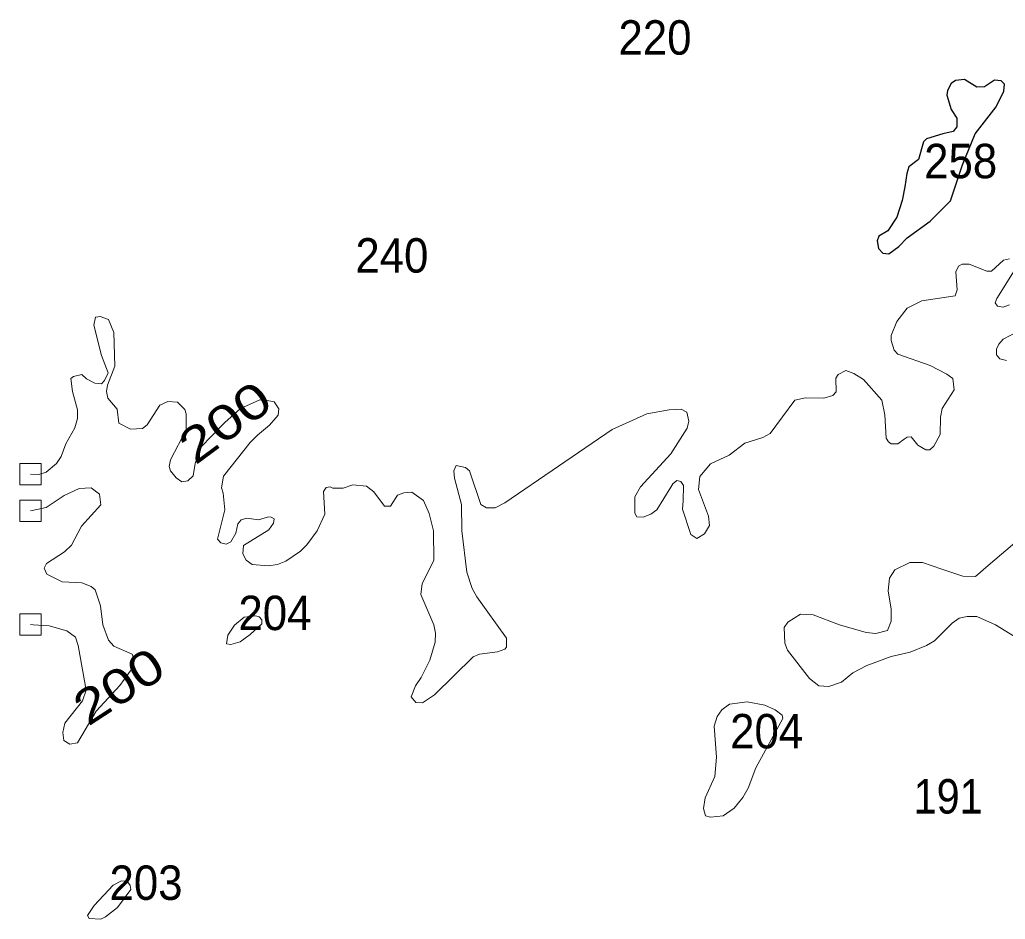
# Model space of a CAD drawing. Extents: x 499.9 to 555.3, y 9281.5 to 9336.8.
# Drawn here: x 499.95 to 504.528, y 9297.621 to 9301.799 of the extents above; entities that cross this region are included whole.
import ezdxf
from ezdxf.enums import TextEntityAlignment as Align

# ---------------------------------------------------------------- set-up
doc = ezdxf.new("R2010")
doc.units = 0
doc.header["$LTSCALE"] = 0.064
for name, color, linetype, lineweight in [('1', 7, 'Continuous', 25), ('2', 7, 'Continuous', 13), ('62', 7, 'Continuous', 13)]:
    doc.layers.add(name, color=color, linetype=linetype, lineweight=lineweight)
doc.layers.add('21', color=7, linetype='Continuous')
doc.layers.add('61', color=7, linetype='Continuous')

msp = doc.modelspace()

# ---------------------------------------------------------------- linework, layer by layer
at = {"layer": '1'}
msp.add_lwpolyline([(504.1796, 9300.8642), (504.2734, 9300.9584), (504.329, 9301.1256), (504.3885, 9301.2695), (504.4858, 9301.3947), (504.5208, 9301.4678), (504.5246, 9301.4992), (504.509, 9301.515), (504.4779, 9301.5182), (504.4309, 9301.4874), (504.396, 9301.4855), (504.3393, 9301.5216), (504.2966, 9301.5169), (504.2759, 9301.5031), (504.2588, 9301.47), (504.2569, 9301.4494), (504.276, 9301.3819), (504.3026, 9301.342), (504.3024, 9301.3009), (504.2863, 9301.2798), (504.2384, 9301.2693), (504.1626, 9301.2456), (504.1474, 9301.2317), (504.1248, 9301.1502), (504.0797, 9301.1159), (504.0707, 9301.0856), (504.0618, 9301.0233), (504.0494, 9300.9591), (504.0241, 9300.8822), (503.9817, 9300.8184), (503.9407, 9300.7934), (503.9328, 9300.7716), (503.9389, 9300.7364), (503.9585, 9300.715), (503.9867, 9300.7111), (504.0329, 9300.7458), (504.0722, 9300.7865)], close=True, dxfattribs=at)
at = {"layer": '2'}
for points in [[(504.2841, 9300.1327), (504.2567, 9300.1531), (504.1788, 9300.1931), (504.0292, 9300.2456), (504.0111, 9300.2648), (503.9975, 9300.3091), (503.9977, 9300.332), (504.0249, 9300.3981), (504.0717, 9300.4597), (504.1398, 9300.4934), (504.2946, 9300.5164), (504.3043, 9300.5449), (504.2984, 9300.628), (504.3111, 9300.6543), (504.3271, 9300.6634), (504.3602, 9300.6638), (504.4428, 9300.6318), (504.4638, 9300.6307), (504.5191, 9300.6825), (504.548, 9300.6884)], [(504.5696, 9300.6332), (504.4893, 9300.5049), (504.4816, 9300.4837), (504.4919, 9300.4689), (504.5181, 9300.4642), (504.5475, 9300.4749)], [(500, 9299.6881), (500.0388, 9299.6869), (500.0733, 9299.6981), (500.1216, 9299.7377), (500.1424, 9299.7701), (500.1644, 9299.829), (500.2058, 9299.9043), (500.2188, 9299.9463), (500.2189, 9299.9869), (500.1947, 9300.0722), (500.1878, 9300.1327), (500.1997, 9300.1425), (500.2379, 9300.1511), (500.2604, 9300.131), (500.2986, 9300.1118), (500.3294, 9300.1074), (500.3441, 9300.123), (500.361, 9300.1597), (500.33, 9300.2403), (500.2936, 9300.3797), (500.3026, 9300.4173), (500.3235, 9300.4209), (500.363, 9300.406), (500.3874, 9300.3468), (500.3917, 9300.1899), (500.3577, 9300.1018), (500.353, 9300.0726), (500.3598, 9300.0413), (500.4032, 9299.9906), (500.4108, 9299.9254), (500.4641, 9299.8972), (500.5197, 9299.9004), (500.5419, 9299.9178), (500.6012, 9300.0082), (500.6384, 9300.0254), (500.6836, 9300.0222), (500.7168, 9299.9892), (500.7234, 9299.9692), (500.723, 9299.8942), (500.6503, 9299.7544), (500.644, 9299.7244), (500.6504, 9299.7036), (500.6762, 9299.6707), (500.7026, 9299.6525), (500.7309, 9299.6578), (500.7562, 9299.6803), (500.7644, 9299.738), (500.7879, 9299.81), (500.9028, 9299.929), (500.9755, 9299.993), (501.065, 9300.0342), (501.0917, 9300.0326), (501.1317, 9300.0243), (501.1532, 9299.9912), (501.1498, 9299.9621), (501.1098, 9299.9162), (501.0546, 9299.87), (501.0207, 9299.8361), (500.8971, 9299.6789), (500.8875, 9299.6254), (500.8955, 9299.6008), (500.9032, 9299.523), (500.8687, 9299.3861), (500.8844, 9299.3688), (500.909, 9299.3635), (500.9308, 9299.3739), (500.9541, 9299.4147), (500.9629, 9299.4583), (500.9782, 9299.477), (501.0053, 9299.4845), (501.0595, 9299.4768), (501.1062, 9299.4908), (501.1187, 9299.4893), (501.1315, 9299.4811), (501.1292, 9299.4607), (501.1078, 9299.4302), (500.9901, 9299.3577), (500.9862, 9299.3178), (501.0021, 9299.2891), (501.0298, 9299.2683), (501.1052, 9299.2619), (501.1476, 9299.2682), (501.1866, 9299.2842), (501.254, 9299.3309), (501.284, 9299.3596), (501.331, 9299.4245), (501.3677, 9299.5031), (501.3618, 9299.608), (501.3738, 9299.626), (501.3922, 9299.6302), (501.404, 9299.6233), (501.4521, 9299.6232), (501.4977, 9299.6391), (501.5614, 9299.6327), (501.595, 9299.6061)], [(504.5895, 9300.352), (504.5177, 9300.3149), (504.4975, 9300.2928), (504.4877, 9300.2689), (504.4869, 9300.2428), (504.5024, 9300.2242), (504.5329, 9300.2166)], [(501.7342, 9299.6023), (501.7715, 9299.6054), (501.8251, 9299.5656), (501.8524, 9299.5053), (501.8723, 9299.425), (501.8741, 9299.288), (501.8192, 9299.1808), (501.8137, 9299.1294), (501.8739, 9298.9889), (501.882, 9298.9499), (501.8803, 9298.9078), (501.8547, 9298.8251), (501.8155, 9298.7437), (501.7883, 9298.7048), (501.768, 9298.654), (501.7893, 9298.6275), (501.8215, 9298.6269), (501.8769, 9298.6631), (502.0556, 9298.84), (502.085, 9298.8529), (502.1687, 9298.863), (502.2034, 9298.8753), (502.2114, 9298.8855), (502.2106, 9298.9259), (502.0728, 9299.1193), (502.0522, 9299.1576), (502.027, 9299.2332), (502.003, 9299.425), (502.0014, 9299.5476), (501.9693, 9299.6693), (501.9667, 9299.7042), (501.9769, 9299.7292), (502.0204, 9299.72), (502.0398, 9299.7035), (502.0914, 9299.548), (502.1176, 9299.5323), (502.1592, 9299.5322), (502.203, 9299.5549), (502.7025, 9299.8957), (502.8635, 9299.9689), (502.966, 9299.9876), (503.023, 9299.9906), (503.0491, 9299.9762), (503.0583, 9299.9348), (503.0506, 9299.9023), (502.975, 9299.7832), (502.8328, 9299.6301), (502.8068, 9299.5827), (502.807, 9299.5071), (502.8172, 9299.4896), (502.8457, 9299.4883), (502.8809, 9299.502), (502.9095, 9299.5225), (502.9746, 9299.628), (502.9838, 9299.643), (503.0019, 9299.6583), (503.021, 9299.6537), (503.0329, 9299.6357), (503.0316, 9299.5651), (503.0283, 9299.5261), (503.0678, 9299.4089), (503.0956, 9299.3897), (503.1305, 9299.4106), (503.1535, 9299.4505), (503.1499, 9299.4928), (503.103, 9299.6178), (503.1089, 9299.6773), (503.1587, 9299.736), (503.2454, 9299.7773), (503.3178, 9299.8322), (503.4021, 9299.8589), (503.4363, 9299.8775), (503.5503, 9300.0318), (503.5996, 9300.0436), (503.6853, 9300.0419), (503.7266, 9300.0532), (503.7427, 9300.0703), (503.7411, 9300.134), (503.752, 9300.1506), (503.788, 9300.1692), (503.8248, 9300.1566), (503.8693, 9300.1281), (503.9552, 9300.0314), (503.9683, 9299.964), (503.9749, 9299.8555), (503.9854, 9299.8388), (503.9978, 9299.8289), (504.0285, 9299.83), (504.0577, 9299.8514), (504.0717, 9299.8606), (504.0902, 9299.8625), (504.121, 9299.8225), (504.1596, 9299.8017), (504.177, 9299.8018), (504.1956, 9299.8189)], [(504.1956, 9299.8189), (504.2262, 9299.8733), (504.2266, 9299.9534), (504.2344, 9299.9932), (504.2913, 9300.0793), (504.2841, 9300.1327)], [(500, 9298.99), (500.0126, 9298.9892), (500.0862, 9298.9845), (500.1695, 9298.9607), (500.2092, 9298.9318), (500.2221, 9298.8931), (500.2588, 9298.6855), (500.241, 9298.6359), (500.1596, 9298.5318), (500.1497, 9298.4878), (500.1555, 9298.4519), (500.1833, 9298.4336), (500.2189, 9298.4399), (500.3044, 9298.5876), (500.4155, 9298.7066), (500.475, 9298.7899), (500.4828, 9298.8267), (500.4723, 9298.8519), (500.3868, 9298.8897), (500.3619, 9298.9172), (500.3368, 9298.9881), (500.3254, 9299.0772), (500.3011, 9299.1509), (500.2825, 9299.1663), (500.238, 9299.1837), (500.1473, 9299.1878), (500.0765, 9299.2235), (500.0633, 9299.2512), (500.0737, 9299.2738), (500.1578, 9299.3283), (500.1902, 9299.359), (500.237, 9299.4471), (500.3263, 9299.5456), (500.3209, 9299.5955), (500.2824, 9299.6244), (500.2259, 9299.6216), (500.157, 9299.589), (500.0732, 9299.5329), (500.0073, 9299.5198), (500, 9299.5184), (500, 9299.5183)], [(501.595, 9299.6061), (501.6451, 9299.5403), (501.6717, 9299.5394), (501.7045, 9299.5901), (501.7342, 9299.6023)], [(504.5932, 9299.3865), (504.449, 9299.2645), (504.3896, 9299.213), (504.3313, 9299.2147), (504.2328, 9299.2467), (504.1437, 9299.2777), (504.0848, 9299.2777), (504.0149, 9299.2437), (503.9897, 9299.2059), (503.9847, 9299.1466), (503.9973, 9299.0606), (503.9973, 9299.0054), (503.9803, 9298.9616), (503.927, 9298.9486), (503.882, 9298.9533), (503.7579, 9298.9884), (503.6362, 9299.0353), (503.5769, 9299.0375), (503.5181, 9299.0003), (503.5011, 9298.9767), (503.5039, 9298.9027), (503.5164, 9298.8711), (503.6186, 9298.7399), (503.6617, 9298.7049), (503.7084, 9298.7019), (503.7669, 9298.7217), (503.8205, 9298.7663), (503.8852, 9298.8), (503.9983, 9298.8417), (504.0864, 9298.8609), (504.1628, 9298.8927), (504.1994, 9298.915), (504.2816, 9298.9956), (504.3139, 9299.0196), (504.3514, 9299.0279), (504.3952, 9299.0277), (504.4828, 9298.9888), (504.6508, 9298.885)]]:
    msp.add_lwpolyline(points, dxfattribs=at)
for points in [[(500.9924, 9299.0235), (500.9472, 9298.9877), (500.9166, 9298.94), (500.9099, 9298.8996), (500.9307, 9298.8968), (500.9735, 9298.9101), (501.0201, 9298.9431), (501.0751, 9298.9937), (501.0753, 9299.0111), (501.062, 9299.0253), (501.0474, 9299.0297)], [(503.3689, 9298.3242), (503.4943, 9298.5539), (503.4912, 9298.5687), (503.4594, 9298.5939), (503.4116, 9298.6156), (503.3288, 9298.6315), (503.2469, 9298.6206), (503.2117, 9298.5938), (503.1892, 9298.5621), (503.1763, 9298.5178), (503.1864, 9298.3742), (503.1792, 9298.2845), (503.1347, 9298.1853), (503.1255, 9298.135), (503.1351, 9298.1019), (503.1587, 9298.0952), (503.2175, 9298.1018), (503.2687, 9298.1371), (503.3093, 9298.1869), (503.3336, 9298.2305)], [(500.3485, 9297.6329), (500.4045, 9297.6756), (500.4654, 9297.7592), (500.4625, 9297.7771), (500.4494, 9297.7974), (500.4235, 9297.7989), (500.384, 9297.7794), (500.2959, 9297.6854), (500.265, 9297.6381), (500.2725, 9297.625), (500.3272, 9297.6209)]]:
    msp.add_lwpolyline(points, close=True, dxfattribs=at)
at = {"layer": '62'}
for points in [[(499.95, 9299.7381), (500.05, 9299.7381), (500.05, 9299.6381), (499.95, 9299.6381)], [(499.95, 9299.5683), (500.05, 9299.5683), (500.05, 9299.4683), (499.95, 9299.4683)], [(499.95, 9299.04), (500.05, 9299.04), (500.05, 9298.94), (499.95, 9298.94)]]:
    msp.add_lwpolyline(points, close=True, dxfattribs=at)

# ---------------------------------------------------------------- texts
at = {"layer": '21'}
for s, width, p in [('220', 0.95, (502.7314, 9301.6368)), ('258', 0.95, (504.1512, 9301.0628)), ('240', 0.95, (501.5092, 9300.6245)), ('204', 0.95, (500.966, 9298.964)), ('204', 0.95, (503.25, 9298.4146)), ('191', 0.9, (504.1018, 9298.1121)), ('203', 0.95, (500.3672, 9297.7109))]:
    msp.add_text(s, height=0.16, dxfattribs=dict(at, width=width)).set_placement(p)
at = {"layer": '61'}
for rotation, width, p in [(36.529, 1.3, (500.9513, 9299.8653)), (33.119, 1.25, (500.4542, 9298.6364))]:
    msp.add_text('200', height=0.16, rotation=rotation, dxfattribs=dict(at, width=width)).set_placement(p, align=Align.CENTER)

doc.saveas('drawing.dxf')
